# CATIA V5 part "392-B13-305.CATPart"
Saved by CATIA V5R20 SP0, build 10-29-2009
Part number: 392-B13-305
Definition: NONE
Nomenclature: 392-B13-305
Source: Unknown
Description: 392-B13-305
Bounding box of the stored display mesh (mm): x 0 to 305, y -6.144 to 6.144, z -6.1 to 5.947
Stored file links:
  C:\Users\Utente\Desktop\IO LAVORO\3D X SITO CF\X SITO\3D files 392B\392-B13-305.CATPart
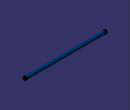
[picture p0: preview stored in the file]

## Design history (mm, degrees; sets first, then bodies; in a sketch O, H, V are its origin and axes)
Body1 "392-B13-305" (main body)
  Solid1: solid without history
